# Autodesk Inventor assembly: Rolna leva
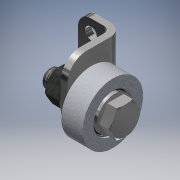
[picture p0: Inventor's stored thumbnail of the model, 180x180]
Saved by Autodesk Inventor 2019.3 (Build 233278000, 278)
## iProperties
Created: 2019-02
Part Number: Rolna leva
Material: Všeobecné
Document SubType Name: Assembly
Designer: B-hon
Author: B-hon
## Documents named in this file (5)
- C:\Users\B-hon\OneDrive\Plocha\Bakalářka2\Rolna leva.iam
- C:\Users\B-hon\OneDrive\Plocha\Bakalářka\Rolna.iam
- C:\Users\B-hon\OneDrive\Documents\Inventor\Content Center Files\R2019\cs-CZ\DIN 125-1  A\DIN 125 - A 8,4.ipt
- C:\Users\B-hon\OneDrive\Documents\Inventor\Content Center Files\R2019\cs-CZ\CSN EN 24034\ISO 4034 - M8CSN EN.ipt
- C:\Users\B-hon\OneDrive\Plocha\Bakalářka2\Držák rolny2.ipt
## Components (4 placed, 4 different names)
1. Rolna:1 [sub-assembly] — Proti sobě:7, Proti sobě:8, Proti sobě:9, Proti sobě:10
2. DIN 125-1 A A 8,4:1 — Proti sobě:7, Vložit:12, Proti sobě:11
3. CSN EN 24034 M8:1 — Vložit:12
4. Držák rolny2:1 — Proti sobě:8, Proti sobě:9, Proti sobě:10, Proti sobě:11
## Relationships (6: Mate 5, Insert 1)
- Proti sobě:7 [Mate]: Rolna:1 ↔ DIN 125-1 A A 8,4:1
- Vložit:12 [Insert]: DIN 125-1 A A 8,4:1 ↔ CSN EN 24034 M8:1
- Proti sobě:8 [Mate]: Rolna:1 ↔ Držák rolny2:1
- Proti sobě:9 [Mate]: Rolna:1 ↔ Držák rolny2:1
- Proti sobě:10 [Mate]: Rolna:1 ↔ Držák rolny2:1
- Proti sobě:11 [Mate]: DIN 125-1 A A 8,4:1 ↔ Držák rolny2:1
